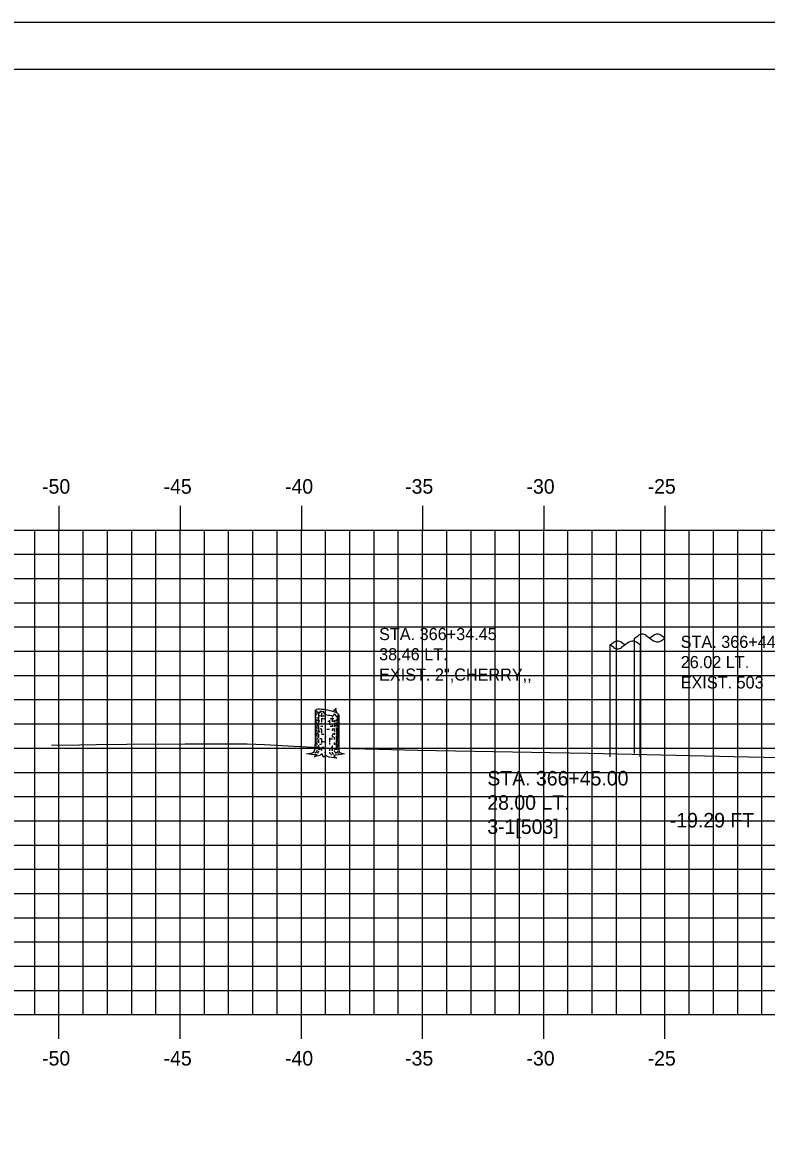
# Model space of a CAD drawing. Extents: x 1147412 to 1147582, y 608981 to 609091.
# Drawn here: x 1147443.2 to 1147473.88, y 609044.65 to 609091.28 of the extents above; entities that cross this region are included whole.
import ezdxf

# ---------------------------------------------------------------- set-up
doc = ezdxf.new("R2010")
doc.units = 0
for name, color, linetype in [('BORDER', 7, 'Continuous'), ('D_Text_Monospaced', 7, 'Continuous'), ('D_Text_Standard', 7, 'Continuous'), ('D_Utilities_Pole_Joint', 7, 'Continuous'), ('H_V ANNOTATION', 7, 'Continuous'), ('MAJOR', 7, 'Continuous'), ('MINOR', 7, 'Continuous'), ('PLOT BOUNDARY', 7, 'Continuous'), ('S_Roadway_Centerline', 7, 'Continuous'), ('S_Trees_Decid_NonPay', 7, 'Continuous'), ('S_Utilities_Pole_Power', 7, 'Continuous')]:
    doc.layers.add(name, color=color, linetype=linetype)

msp = doc.modelspace()

# ---------------------------------------------------------------- linework, layer by layer
at = {"layer": 'BORDER'}
msp.add_lwpolyline([(1147419.698, 608984.335), (1147579.698, 608984.335), (1147579.698, 609089.335), (1147419.698, 609089.335)], close=True, dxfattribs=at)
at = {"layer": 'D_Utilities_Pole_Joint'}
for p, q in [((1147468.447, 609065.876), (1147468.604, 609065.986)), ((1147468.447, 609061.118), (1147468.447, 609065.876)), ((1147468.916, 609065.986), (1147469.072, 609065.876)), ((1147469.228, 609065.986), (1147469.072, 609065.876)), ((1147469.072, 609065.876), (1147469.228, 609065.765)), ((1147469.697, 609065.876), (1147469.541, 609065.986)), ((1147469.541, 609065.765), (1147469.697, 609065.876)), ((1147469.697, 609061.118), (1147469.697, 609065.876))]:
    msp.add_line(p, q, dxfattribs=at)
for centre, start, end in [((1147468.76, 609065.765), 90, 125.2644), ((1147468.76, 609065.765), 54.7356, 90), ((1147469.385, 609065.765), 90, 125.2644), ((1147469.385, 609065.986), 234.7356, 270), ((1147469.385, 609065.765), 54.7356, 90), ((1147469.385, 609065.986), 270, 305.2644)]:
    msp.add_arc(centre, 0.271, start, end, dxfattribs=at)
at = {"layer": 'MAJOR'}
for p, q in [((1147444.697, 609071.337), (1147444.697, 609070.335)), ((1147449.697, 609071.337), (1147449.697, 609070.335)), ((1147454.697, 609071.337), (1147454.697, 609070.335)), ((1147459.697, 609071.337), (1147459.697, 609070.335)), ((1147464.697, 609071.337), (1147464.697, 609070.335)), ((1147469.697, 609071.337), (1147469.697, 609070.335)), ((1147424.697, 609070.335), (1147564.697, 609070.335)), ((1147424.697, 609070.335), (1147564.697, 609070.335)), ((1147444.697, 609050.335), (1147444.697, 609070.335)), ((1147449.697, 609050.335), (1147449.697, 609070.335)), ((1147454.697, 609050.335), (1147454.697, 609070.335)), ((1147459.697, 609050.335), (1147459.697, 609070.335)), ((1147464.697, 609050.335), (1147464.697, 609070.335)), ((1147469.697, 609050.335), (1147469.697, 609070.335)), ((1147424.697, 609065.335), (1147564.697, 609065.335)), ((1147424.697, 609060.335), (1147564.697, 609060.335)), ((1147424.697, 609055.335), (1147564.697, 609055.335)), ((1147424.697, 609050.335), (1147564.697, 609050.335)), ((1147424.697, 609050.335), (1147564.697, 609050.335)), ((1147444.697, 609049.333), (1147444.697, 609050.335)), ((1147449.697, 609049.333), (1147449.697, 609050.335)), ((1147454.697, 609049.333), (1147454.697, 609050.335)), ((1147459.697, 609049.333), (1147459.697, 609050.335)), ((1147464.697, 609049.333), (1147464.697, 609050.335)), ((1147469.697, 609049.333), (1147469.697, 609050.335))]:
    msp.add_line(p, q, dxfattribs=at)
at = {"layer": 'MINOR'}
for p, q in [((1147443.697, 609050.335), (1147443.697, 609070.335)), ((1147445.697, 609050.335), (1147445.697, 609070.335)), ((1147446.697, 609050.335), (1147446.697, 609070.335)), ((1147447.697, 609050.335), (1147447.697, 609070.335)), ((1147448.697, 609050.335), (1147448.697, 609070.335)), ((1147450.697, 609050.335), (1147450.697, 609070.335)), ((1147451.697, 609050.335), (1147451.697, 609070.335)), ((1147452.697, 609050.335), (1147452.697, 609070.335)), ((1147453.697, 609050.335), (1147453.697, 609070.335)), ((1147455.697, 609050.335), (1147455.697, 609070.335)), ((1147456.697, 609050.335), (1147456.697, 609070.335)), ((1147457.697, 609050.335), (1147457.697, 609070.335)), ((1147458.697, 609050.335), (1147458.697, 609070.335)), ((1147460.697, 609050.335), (1147460.697, 609070.335)), ((1147461.697, 609050.335), (1147461.697, 609070.335)), ((1147462.697, 609050.335), (1147462.697, 609070.335)), ((1147463.697, 609050.335), (1147463.697, 609070.335)), ((1147465.697, 609050.335), (1147465.697, 609070.335)), ((1147466.697, 609050.335), (1147466.697, 609070.335)), ((1147467.697, 609050.335), (1147467.697, 609070.335)), ((1147468.697, 609050.335), (1147468.697, 609070.335)), ((1147470.697, 609050.335), (1147470.697, 609070.335)), ((1147471.697, 609050.335), (1147471.697, 609070.335)), ((1147472.697, 609050.335), (1147472.697, 609070.335)), ((1147473.697, 609050.335), (1147473.697, 609070.335)), ((1147424.697, 609069.335), (1147564.697, 609069.335)), ((1147424.697, 609068.335), (1147564.697, 609068.335)), ((1147424.697, 609067.335), (1147564.697, 609067.335)), ((1147424.697, 609066.335), (1147564.697, 609066.335)), ((1147424.697, 609064.335), (1147564.697, 609064.335)), ((1147424.697, 609063.335), (1147564.697, 609063.335)), ((1147424.697, 609062.335), (1147564.697, 609062.335)), ((1147424.697, 609061.335), (1147564.697, 609061.335)), ((1147424.697, 609059.335), (1147564.697, 609059.335)), ((1147424.697, 609058.335), (1147564.697, 609058.335)), ((1147424.697, 609057.335), (1147564.697, 609057.335)), ((1147424.697, 609056.335), (1147564.697, 609056.335)), ((1147424.697, 609054.335), (1147564.697, 609054.335)), ((1147424.697, 609053.335), (1147564.697, 609053.335)), ((1147424.697, 609052.335), (1147564.697, 609052.335)), ((1147424.697, 609051.335), (1147564.697, 609051.335))]:
    msp.add_line(p, q, dxfattribs=at)
at = {"layer": 'PLOT BOUNDARY'}
msp.add_lwpolyline([(1147411.604, 608981.276), (1147581.604, 608981.276), (1147581.604, 609091.276), (1147411.604, 609091.276)], close=True, dxfattribs=at)
at = {"layer": 'S_Roadway_Centerline'}
msp.add_lwpolyline([(1147444.386, 609061.455), (1147445.539, 609061.474), (1147446.244, 609061.484), (1147447.496, 609061.5), (1147449.909, 609061.516), (1147452.466, 609061.513), (1147453.179, 609061.479), (1147454.407, 609061.419), (1147455.714, 609061.351), (1147459.49, 609061.244), (1147466.538, 609061.124), (1147473.137, 609060.973), (1147480.324, 609060.826)], dxfattribs=at)
at = {"layer": 'S_Trees_Decid_NonPay'}
for p, q in [((1147455.339, 609062.843), (1147455.339, 609062.749)), ((1147455.339, 609062.522), (1147455.339, 609062.44)), ((1147455.407, 609062.757), (1147455.407, 609062.456)), ((1147455.407, 609062.427), (1147455.407, 609062.296)), ((1147455.526, 609062.774), (1147455.526, 609062.625)), ((1147455.526, 609062.577), (1147455.526, 609062.409)), ((1147455.673, 609062.728), (1147455.673, 609062.621)), ((1147455.853, 609062.492), (1147455.853, 609062.291)), ((1147455.97, 609062.675), (1147455.97, 609062.597)), ((1147455.97, 609062.51), (1147455.97, 609062.425)), ((1147456.057, 609062.492), (1147456.057, 609062.405)), ((1147456.128, 609062.665), (1147456.128, 609062.613)), ((1147456.128, 609062.51), (1147456.128, 609062.427)), ((1147456.17, 609062.67), (1147456.17, 609062.452)), ((1147456.197, 609062.6), (1147456.197, 609062.518)), ((1147456.197, 609062.448), (1147456.197, 609062.318)), ((1147455.339, 609062.37), (1147455.339, 609062.119)), ((1147455.339, 609062.036), (1147455.339, 609061.806)), ((1147455.407, 609062.262), (1147455.407, 609061.981)), ((1147455.526, 609062.102), (1147455.526, 609061.954)), ((1147455.673, 609062.392), (1147455.673, 609062.306)), ((1147455.673, 609062.271), (1147455.673, 609062.201)), ((1147455.97, 609062.314), (1147455.97, 609062.213)), ((1147455.97, 609062.129), (1147455.97, 609062.053)), ((1147456.057, 609062.335), (1147456.057, 609062.213)), ((1147456.057, 609062.138), (1147456.057, 609062.024)), ((1147456.057, 609061.962), (1147456.057, 609061.88)), ((1147456.128, 609062.392), (1147456.128, 609062.318)), ((1147456.128, 609062.291), (1147456.128, 609062.232)), ((1147456.128, 609062.179), (1147456.128, 609061.997)), ((1147456.128, 609061.966), (1147456.128, 609061.884)), ((1147456.17, 609062.383), (1147456.17, 609062.232)), ((1147456.17, 609062.127), (1147456.17, 609062.049)), ((1147456.17, 609062.022), (1147456.17, 609061.915)), ((1147456.197, 609062.296), (1147456.197, 609062.114)), ((1147456.197, 609062.067), (1147456.197, 609061.82)), ((1147455.339, 609061.736), (1147455.339, 609061.575)), ((1147455.339, 609061.558), (1147455.339, 609061.453)), ((1147455.407, 609061.911), (1147455.407, 609061.766)), ((1147455.407, 609061.696), (1147455.407, 609061.555)), ((1147455.526, 609061.684), (1147455.526, 609061.532)), ((1147455.673, 609061.868), (1147455.673, 609061.645)), ((1147455.853, 609061.754), (1147455.853, 609061.567)), ((1147455.853, 609061.536), (1147455.853, 609061.483)), ((1147455.97, 609061.868), (1147455.97, 609061.77)), ((1147456.057, 609061.793), (1147456.057, 609061.696)), ((1147456.057, 609061.567), (1147456.057, 609061.468)), ((1147456.128, 609061.83), (1147456.128, 609061.66)), ((1147456.128, 609061.626), (1147456.128, 609061.347)), ((1147456.17, 609061.88), (1147456.17, 609061.779)), ((1147456.17, 609061.753), (1147456.17, 609061.571)), ((1147456.17, 609061.468), (1147456.17, 609061.276)), ((1147456.197, 609061.801), (1147456.197, 609061.707)), ((1147456.199, 609061.654), (1147456.198, 609061.394)), ((1147455.339, 609061.417), (1147455.339, 609061.293)), ((1147455.407, 609061.213), (1147455.365, 609061.116)), ((1147455.407, 609061.453), (1147455.407, 609061.272)), ((1147455.526, 609061.32), (1147455.526, 609061.242)), ((1147455.673, 609061.312), (1147455.673, 609061.245)), ((1147455.713, 609061.026), (1147455.678, 609061.171)), ((1147455.853, 609061.307), (1147455.853, 609061.217)), ((1147455.97, 609061.446), (1147455.97, 609061.221)), ((1147456.057, 609061.339), (1147456.057, 609061.28)), ((1147456.128, 609061.294), (1147456.128, 609061.268)), ((1147456.168, 609061.229), (1147456.203, 609061.178)), ((1147456.25, 609061.108), (1147456.183, 609061.139)), ((1147456.197, 609061.355), (1147456.197, 609061.281))]:
    msp.add_line(p, q, dxfattribs=at)
for points in [[(1147456.239, 609062.707), (1147456.239, 609061.295), (1147456.261, 609061.147), (1147456.464, 609061.104), (1147456.325, 609061.068), (1147456.106, 609061.05), (1147456.037, 609061.007), (1147456.158, 609060.918), (1147455.827, 609060.961), (1147455.713, 609061.026), (1147455.621, 609060.965), (1147455.565, 609061.044), (1147455.573, 609061.081), (1147455.512, 609061.083), (1147455.46, 609061.026), (1147455.228, 609060.974), (1147455.355, 609061.062), (1147455.223, 609061.064), (1147454.915, 609061.102), (1147455.153, 609061.133), (1147455.231, 609061.19), (1147455.27, 609061.312), (1147455.287, 609061.665), (1147455.287, 609062.899)], [(1147455.651, 609062.733), (1147455.643, 609062.8), (1147455.619, 609062.805), (1147455.61, 609062.839), (1147455.579, 609062.825), (1147455.565, 609062.839), (1147455.541, 609062.816), (1147455.518, 609062.825), (1147455.505, 609062.874), (1147455.497, 609062.831), (1147455.466, 609062.839), (1147455.463, 609062.788)], [(1147456.144, 609062.788), (1147456.14, 609062.883), (1147456.125, 609062.856), (1147456.125, 609062.977), (1147456.104, 609062.913), (1147456.09, 609062.946), (1147456.073, 609062.89), (1147456.057, 609062.908), (1147456.039, 609062.899), (1147456.02, 609062.832)], [(1147456.121, 609062.664), (1147456.104, 609062.726), (1147456.082, 609062.714), (1147456.051, 609062.749), (1147456.018, 609062.671)], [(1147455.336, 609061.25), (1147455.328, 609061.173), (1147455.25, 609061.124)], [(1147455.861, 609061.167), (1147455.861, 609061.131), (1147455.913, 609061.1), (1147455.93, 609061.05)], [(1147455.973, 609061.173), (1147455.979, 609061.104), (1147456.042, 609061.091)], [(1147456.121, 609061.139), (1147456.077, 609061.173), (1147456.069, 609061.221)], [(1147456.199, 609061.155), (1147456.121, 609061.139), (1147456.104, 609061.095)]]:
    msp.add_lwpolyline(points, dxfattribs=at)
for centre, radius, start, end in [((1147455.305, 609062.899), 0.0179, 152.1168, 168.1723), ((1147455.305, 609062.899), 0.0179, 168.1723, 184.2278), ((1147455.311, 609062.9), 0.0237, 184.2278, 198.1723), ((1147455.321, 609062.903), 0.0336, 198.1723, 216.9486), ((1147455.311, 609062.896), 0.0237, 138.1723, 152.1168), ((1147455.318, 609062.89), 0.0336, 119.396, 138.1723), ((1147455.368, 609062.939), 0.0935, 216.9486, 228.1723), ((1147455.347, 609062.838), 0.0935, 108.1723, 119.396), ((1147455.521, 609063.109), 0.322, 228.1723, 250.2902), ((1147455.419, 609062.621), 0.322, 86.0543, 108.1723), ((1147455.268, 609060.441), 2.507, 78.1723, 86.0543), ((1147455.268, 609060.441), 2.507, 70.2902, 78.1723), ((1147455.306, 609062.752), 0.0191, 163.9485, 180), ((1147455.306, 609062.752), 0.0191, 180, 196.0515), ((1147455.306, 609062.538), 0.0191, 163.9485, 180), ((1147455.306, 609062.538), 0.0191, 180, 196.0515), ((1147455.306, 609062.435), 0.0191, 163.9485, 180), ((1147455.306, 609062.435), 0.0191, 180, 196.0515), ((1147455.312, 609062.753), 0.0252, 196.0515, 210), ((1147455.312, 609062.539), 0.0252, 196.0515, 210), ((1147455.312, 609062.436), 0.0252, 196.0515, 210), ((1147455.321, 609062.759), 0.0356, 210, 228.7494), ((1147455.321, 609062.544), 0.0356, 210, 228.7494), ((1147455.321, 609062.442), 0.0356, 210, 228.7494), ((1147455.362, 609062.806), 0.0984, 228.7494, 240), ((1147455.362, 609062.592), 0.0984, 228.7494, 240), ((1147455.362, 609062.489), 0.0984, 228.7494, 240), ((1147455.476, 609063.003), 0.326, 240, 248.3243), ((1147455.476, 609062.789), 0.326, 240, 243.5719), ((1147455.476, 609062.686), 0.326, 240, 243.243), ((1147455.476, 609062.89), 0.326, 240.9099, 257.8036), ((1147455.476, 609062.789), 0.326, 250.4167, 261.8968), ((1147455.476, 609063.003), 0.326, 257.8036, 261.8968), ((1147456.258, 609065.166), 2.507, 250.2902, 251.5281), ((1147455.762, 609065.013), 2.356, 261.8968, 263.2799), ((1147455.762, 609064.799), 2.356, 261.8968, 262.5519), ((1147455.762, 609064.9), 2.356, 264.242, 267.3673), ((1147455.762, 609065.013), 2.356, 265.24, 267.8386), ((1147456.258, 609065.166), 2.507, 255.9987, 258.1723), ((1147456.258, 609065.166), 2.507, 258.1723, 264.5013), ((1147455.762, 609064.799), 2.356, 270.8119, 272.1981), ((1147455.762, 609064.9), 2.356, 273.1481, 276.7734), ((1147455.762, 609064.799), 2.356, 275.0647, 278.1032), ((1147456.048, 609062.789), 0.326, 278.1032, 279.0854), ((1147456.005, 609062.498), 0.322, 48.1723, 70.2902), ((1147456.107, 609062.986), 0.322, 272.4479, 288.1723), ((1147456.048, 609062.89), 0.326, 291.9506, 300), ((1147456.048, 609062.789), 0.326, 291.9506, 300), ((1147456.179, 609062.769), 0.0935, 288.1723, 299.396), ((1147456.162, 609062.693), 0.0984, 300, 311.2506), ((1147456.162, 609062.592), 0.0984, 300, 311.2506), ((1147456.157, 609062.668), 0.0935, 36.9486, 48.1723), ((1147456.208, 609062.717), 0.0336, 299.396, 318.1723), ((1147456.204, 609062.645), 0.0356, 311.2506, 330), ((1147456.204, 609062.544), 0.0356, 311.2506, 330), ((1147456.205, 609062.704), 0.0336, 18.1723, 36.9486), ((1147456.215, 609062.71), 0.0237, 318.1723, 332.1168), ((1147456.213, 609062.64), 0.0252, 330, 343.9485), ((1147456.213, 609062.539), 0.0252, 330, 343.9485), ((1147456.22, 609062.707), 0.0179, 332.1168, 348.1723), ((1147456.215, 609062.707), 0.0237, 4.2278, 18.1723), ((1147456.219, 609062.638), 0.0191, 343.9485, 360), ((1147456.219, 609062.538), 0.0191, 343.9485, 360), ((1147456.219, 609062.435), 0.0191, 343.9485, 360), ((1147456.22, 609062.707), 0.0179, 348.1723, 4.2278), ((1147456.219, 609062.638), 0.0191, 360, 6.1128), ((1147456.219, 609062.538), 0.0191, 360, 6.1128), ((1147456.219, 609062.435), 0.0191, 360, 6.1128), ((1147455.303, 609062), 0.0191, 163.9485, 180), ((1147455.306, 609062.215), 0.0191, 163.9485, 180), ((1147455.306, 609062.215), 0.0191, 180, 196.0515), ((1147455.312, 609062.216), 0.0252, 196.0515, 210), ((1147455.307, 609062.1), 0.0191, 163.9485, 180), ((1147455.307, 609062.1), 0.0191, 180, 196.0515), ((1147455.312, 609062.102), 0.0252, 196.0515, 210), ((1147455.321, 609062.221), 0.0356, 210, 228.7494), ((1147455.322, 609062.107), 0.0356, 210, 228.7494), ((1147455.362, 609062.269), 0.0984, 228.7494, 240), ((1147455.363, 609062.154), 0.0984, 228.7494, 240), ((1147455.474, 609062.251), 0.326, 240, 256.9079), ((1147455.476, 609062.466), 0.326, 240, 245.1545), ((1147455.477, 609062.351), 0.326, 240, 247.8656), ((1147455.476, 609062.581), 0.326, 245.1545, 257.8036), ((1147455.476, 609062.686), 0.326, 251.6831, 257.8036), ((1147455.477, 609062.351), 0.326, 257.6699, 261.8968), ((1147455.763, 609064.361), 2.356, 261.8968, 262.8615), ((1147455.762, 609064.476), 2.356, 262.6588, 264.7911), ((1147455.762, 609064.591), 2.356, 263.2682, 265.6362), ((1147455.762, 609064.696), 2.356, 263.3413, 264.9946), ((1147455.762, 609064.696), 2.356, 266.5036, 267.8386), ((1147455.762, 609064.476), 2.356, 269.5578, 270), ((1147455.762, 609064.476), 2.356, 270, 272.414), ((1147455.762, 609064.696), 2.356, 272.1981, 273.9741), ((1147455.762, 609064.591), 2.356, 273.0067, 275.0647), ((1147455.762, 609064.476), 2.356, 275.0647, 277.1868), ((1147455.762, 609064.591), 2.356, 277.1868, 278.1032), ((1147455.762, 609064.696), 2.356, 277.3838, 278.1032), ((1147456.048, 609062.686), 0.326, 278.1032, 284.0382), ((1147456.048, 609062.581), 0.326, 278.1032, 284.0382), ((1147456.048, 609062.466), 0.326, 284.0382, 300), ((1147456.049, 609062.351), 0.326, 283.9036, 291.8098), ((1147456.048, 609062.581), 0.326, 291.9506, 300), ((1147456.046, 609062.251), 0.326, 292.4049, 300), ((1147456.049, 609062.351), 0.326, 297.0058, 300), ((1147456.16, 609062.054), 0.0984, 300, 311.2506), ((1147456.162, 609062.384), 0.0984, 300, 311.2506), ((1147456.162, 609062.269), 0.0984, 300, 311.2506), ((1147456.163, 609062.154), 0.0984, 300, 311.2506), ((1147456.201, 609062.007), 0.0356, 311.2506, 330), ((1147456.204, 609062.336), 0.0356, 311.2506, 330), ((1147456.204, 609062.221), 0.0356, 311.2506, 330), ((1147456.204, 609062.107), 0.0356, 311.2506, 330), ((1147456.21, 609062.002), 0.0252, 330, 343.9485), ((1147456.213, 609062.331), 0.0252, 330, 343.9485), ((1147456.213, 609062.216), 0.0252, 330, 343.9485), ((1147456.213, 609062.102), 0.0252, 330, 343.9485), ((1147456.216, 609062), 0.0191, 0, 6.1128), ((1147456.216, 609062), 0.0191, 343.9485, 360), ((1147456.219, 609062.33), 0.0191, 343.9485, 360), ((1147456.219, 609062.215), 0.0191, 343.9485, 360), ((1147456.219, 609062.33), 0.0191, 360, 6.1128), ((1147456.219, 609062.215), 0.0191, 360, 6.1128), ((1147456.219, 609062.1), 0.0191, 0, 6.1128), ((1147456.219, 609062.1), 0.0191, 343.9485, 360), ((1147455.297, 609061.465), 0.0191, 163.9485, 180), ((1147455.297, 609061.465), 0.0191, 180, 196.0515), ((1147455.302, 609061.576), 0.0191, 163.9485, 180), ((1147455.302, 609061.576), 0.0191, 180, 196.0515), ((1147455.308, 609061.578), 0.0252, 196.0515, 210), ((1147455.317, 609061.583), 0.0356, 210, 228.7494), ((1147455.306, 609061.895), 0.0191, 163.9485, 180), ((1147455.306, 609061.895), 0.0191, 180, 196.0515), ((1147455.312, 609061.897), 0.0252, 196.0515, 210), ((1147455.321, 609061.902), 0.0356, 210, 228.7494), ((1147455.358, 609061.63), 0.0984, 228.7494, 240), ((1147455.362, 609061.949), 0.0984, 228.7494, 240), ((1147455.472, 609061.827), 0.326, 240, 245.9375), ((1147455.476, 609062.146), 0.326, 240, 245.1545), ((1147455.476, 609062.056), 0.326, 241.939, 253.9183), ((1147455.758, 609063.837), 2.356, 262.2226, 264.4852), ((1147455.762, 609064.066), 2.356, 262.5843, 264.4865), ((1147455.762, 609063.953), 2.356, 264.242, 267.469), ((1147455.76, 609064.261), 2.356, 264.3443, 266.8529), ((1147455.762, 609064.156), 2.356, 267.8386, 269.0054), ((1147455.762, 609064.066), 2.356, 272.1981, 275.2726), ((1147455.76, 609064.261), 2.356, 274.9734, 277.2455), ((1147455.762, 609064.156), 2.356, 275.0647, 276.428), ((1147455.758, 609063.837), 2.356, 277.2863, 278.1032), ((1147456.044, 609061.827), 0.326, 278.1032, 284.7741), ((1147456.048, 609062.146), 0.326, 284.0382, 291.9506), ((1147456.048, 609061.943), 0.326, 284.0382, 291.9506), ((1147456.048, 609062.146), 0.326, 297.1525, 300), ((1147456.158, 609061.63), 0.0984, 300, 311.2506), ((1147456.162, 609061.949), 0.0984, 300, 311.2506), ((1147456.2, 609061.583), 0.0356, 311.2506, 330), ((1147456.204, 609061.902), 0.0356, 311.2506, 330), ((1147456.209, 609061.578), 0.0252, 330, 343.9485), ((1147456.215, 609061.576), 0.0191, 360, 6.1128), ((1147456.215, 609061.576), 0.0191, 343.9485, 360), ((1147456.213, 609061.897), 0.0252, 330, 343.9485), ((1147456.219, 609061.895), 0.0191, 343.9485, 360), ((1147456.219, 609061.895), 0.0191, 360, 6.1128), ((1147456.219, 609061.805), 0.0191, 360, 6.1128), ((1147455.291, 609061.355), 0.0191, 163.9485, 180), ((1147455.291, 609061.355), 0.0191, 180, 196.0515), ((1147455.297, 609061.357), 0.0252, 196.0515, 210), ((1147455.306, 609061.362), 0.0356, 210, 228.7494), ((1147455.303, 609061.467), 0.0252, 196.0515, 210), ((1147455.312, 609061.472), 0.0356, 210, 228.7494), ((1147455.348, 609061.409), 0.0984, 228.7494, 240), ((1147455.353, 609061.52), 0.0984, 228.7494, 240), ((1147455.462, 609061.607), 0.326, 240, 247.9161), ((1147455.467, 609061.717), 0.326, 240, 241.9097), ((1147455.462, 609061.607), 0.326, 260.3834, 261.8968), ((1147455.748, 609063.617), 2.356, 261.8968, 263.5333), ((1147455.753, 609063.727), 2.356, 264.9089, 266.8158), ((1147455.753, 609063.727), 2.356, 274.1864, 275.2829), ((1147455.748, 609063.617), 2.356, 274.5551, 275.4167), ((1147455.748, 609063.617), 2.356, 277.5403, 278.1032), ((1147456.034, 609061.607), 0.326, 278.1032, 294.7094), ((1147456.039, 609061.717), 0.326, 293.6544, 300), ((1147456.148, 609061.409), 0.0984, 300, 311.2506), ((1147456.189, 609061.362), 0.0356, 311.2506, 330), ((1147456.198, 609061.357), 0.0252, 330, 343.9485), ((1147456.204, 609061.355), 0.0191, 343.9485, 360), ((1147456.204, 609061.355), 0.0191, 0, 6.1128)]:
    msp.add_arc(centre, radius, start, end, dxfattribs=at)
at = {"layer": 'S_Utilities_Pole_Power'}
for p, q in [((1147467.43, 609065.592), (1147467.587, 609065.702)), ((1147467.899, 609065.702), (1147468.056, 609065.592)), ((1147468.212, 609065.702), (1147468.056, 609065.592)), ((1147468.68, 609065.592), (1147468.524, 609065.702)), ((1147467.43, 609060.972), (1147467.434, 609065.592)), ((1147467.587, 609065.481), (1147467.43, 609065.592)), ((1147468.056, 609065.592), (1147467.899, 609065.481)), ((1147468.68, 609060.972), (1147468.684, 609065.592))]:
    msp.add_line(p, q, dxfattribs=at)
for centre, start, end in [((1147467.743, 609065.481), 90, 125.2644), ((1147467.743, 609065.481), 54.7356, 90), ((1147468.368, 609065.481), 90, 125.2644), ((1147468.368, 609065.481), 54.7356, 90), ((1147467.743, 609065.702), 234.7356, 270), ((1147467.743, 609065.702), 270, 305.2644)]:
    msp.add_arc(centre, 0.271, start, end, dxfattribs=at)

# ---------------------------------------------------------------- texts
at = {"layer": 'D_Text_Monospaced'}
for s, height, p in [('STA. 366+34.45', 0.49998, (1147457.905, 609065.793)), ('STA. 366+44.47', 0.49998, (1147470.347, 609065.47)), ('38.46 LT.', 0.5, (1147457.905, 609064.959)), ('26.02 LT.', 0.5, (1147470.347, 609064.636)), ('EXIST. 2",CHERRY,,', 0.49998, (1147457.905, 609064.119)), ('EXIST. 503', 0.5, (1147470.347, 609063.796))]:
    msp.add_text(s, height=height, dxfattribs=at).set_placement(p)
at = {"layer": 'D_Text_Standard'}
for s, p in [('STA. 366+45.00', (1147462.369, 609059.792)), ('28.00 LT.', (1147462.369, 609058.79)), ('-19.29 FT', (1147469.898, 609058.061)), ('3-1[503] ', (1147462.369, 609057.794))]:
    msp.add_text(s, height=0.6, dxfattribs=at).set_placement(p)
at = {"layer": 'H_V ANNOTATION'}
for s, p in [('-50', (1147444.002, 609071.835)), ('-45', (1147449.015, 609071.835)), ('-40', (1147454.023, 609071.835)), ('-35', (1147458.978, 609071.835)), ('-30', (1147463.986, 609071.835)), ('-25', (1147468.983, 609071.835)), ('-50', (1147444.002, 609048.235)), ('-45', (1147449.015, 609048.235)), ('-40', (1147454.023, 609048.235)), ('-35', (1147458.978, 609048.235)), ('-30', (1147463.986, 609048.235)), ('-25', (1147468.983, 609048.235))]:
    msp.add_text(s, height=0.6, dxfattribs=at).set_placement(p)

doc.saveas('drawing.dxf')
